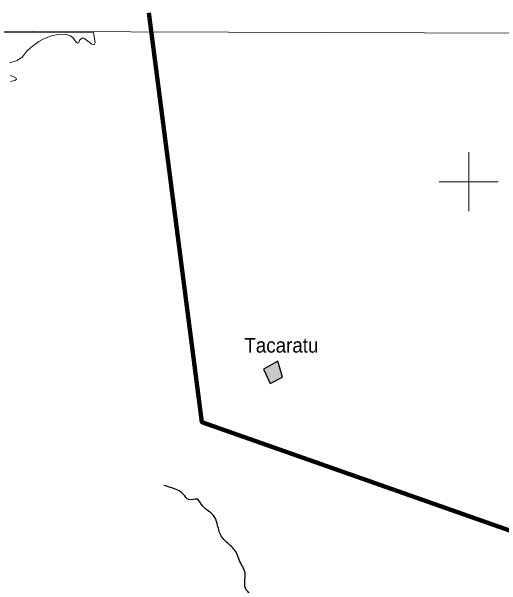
# Model space of a CAD drawing. Extents: x -1643653 to 4543381, y 1624270 to 13878484.
# Drawn here: x 584514 to 601111, y 8986338 to 9005760 of the extents above; entities that cross this region are included whole.
import ezdxf

# ---------------------------------------------------------------- set-up
doc = ezdxf.new("R2010")
doc.units = 0
doc.header["$LTSCALE"] = 200
for name, color, linetype, lineweight in [('1', 7, 'Continuous', 13), ('2', 7, 'Continuous', 13), ('21', 7, 'Continuous', 25), ('24', 7, 'Continuous', 25), ('25', 7, 'Continuous', 13), ('60', 7, 'Continuous', 13), ('9', 7, 'Continuous', 90)]:
    doc.layers.add(name, color=color, linetype=linetype, lineweight=lineweight)
doc.layers.add('41', color=7, linetype='Continuous')

msp = doc.modelspace()

# ---------------------------------------------------------------- hatches: boundary and pattern name
at = {"layer": '21'}
msp.add_hatch(color=256, dxfattribs=at).paths.add_polyline_path([(593047.1, 8993652.8), (593274.2, 8993173.1), (593688.7, 8993391.5), (593540, 8993932.9)])

# ---------------------------------------------------------------- linework, layer by layer
at = {"layer": '1'}
msp.add_lwpolyline([(565303.2, 9005146.6), (664889.8, 9004806.7), (719872.1, 9004543.9), (790635.8, 9004109)], dxfattribs=at)
at = {"layer": '2'}
for p, q in [((600000, 8999000), (600000, 9001000)), ((599000, 9000000), (601000, 9000000))]:
    msp.add_line(p, q, dxfattribs=at)
at = {"layer": '21'}
msp.add_lwpolyline([(593047.1, 8993652.8), (593274.2, 8993173.1), (593688.7, 8993391.5), (593540, 8993932.9)], close=True, dxfattribs=at)
at = {"layer": '24'}
msp.add_spline([(593232.1, 8979422.6), (593198.8, 8979610.9), (593054.8, 8979777.1), (592988.4, 8979954.4), (592877.6, 8980164.9), (592722.6, 8980286.8), (592611.8, 8980375.4), (592456.8, 8980729.9), (592146.7, 8981173.1), (591936.2, 8981505.4), (591869.8, 8981682.7), (591814.4, 8981815.7), (591504.3, 8981904.3), (591316, 8982048.3), (591216.4, 8982148), (591072.4, 8982347.5), (591183.1, 8982491.5), (591526.5, 8982834.9), (591637.2, 8983134.1), (591980.6, 8983211.6), (591958.4, 8983388.9), (591925.2, 8983544), (592146.7, 8983832), (592445.7, 8983865.3), (592589.7, 8983987.2), (592600.8, 8984208.7), (592778, 8984507.9), (592656.1, 8984718.4), (592478.9, 8984851.3), (592456.8, 8985084), (592589.7, 8985228), (592634, 8985394.2), (592645.1, 8985826.3), (592645.1, 8985970.3), (592467.9, 8986191.9), (592423.5, 8986763.6), (592224.2, 8987206.8), (592124.5, 8987461.6), (591847.6, 8987760.7), (591604, 8988037.7), (591482.1, 8988436.5), (591360.3, 8988702.4), (590950.5, 8989079.1), (590806.6, 8989256.4), (590518.6, 8989245.3), (590341.4, 8989422.6), (590031.3, 8989610.9), (589676.9, 8989721.7)], degree=3, dxfattribs=at)
at = {"layer": '25'}
msp.add_line((587296.7, 9005052), (574348.1, 9005079.3), dxfattribs=at)
for points in [[(584458.5, 9004027.7), (584711.2, 9004098.9), (584888.4, 9004222.2), (585025.2, 9004408.7), (585173.7, 9004544.1), (585437.6, 9004740.9), (585593, 9004823), (585860.5, 9004930.9), (586094, 9004976.5), (586360.6, 9004989.5), (586505.2, 9004940), (586587.3, 9004879.5), (586702.2, 9004719.4), (586749.8, 9004689.2), (586792.6, 9004706), (586819.4, 9004784.7), (586914.3, 9004864.1), (586966.1, 9004855.3), (587240.7, 9004654.4), (587315.8, 9004635.1), (587350.6, 9004699.9), (587296.7, 9005052)], [(584458.5, 9004027.7), (584711.2, 9004098.9), (584888.4, 9004222.2), (585025.2, 9004408.7), (585173.7, 9004544.1), (585437.6, 9004740.9), (585593, 9004823), (585860.5, 9004930.9), (586094, 9004976.5), (586360.6, 9004989.5), (586505.2, 9004940), (586587.3, 9004879.5), (586702.2, 9004719.4), (586749.8, 9004689.2), (586792.6, 9004706), (586819.4, 9004784.7), (586914.3, 9004864.1), (586966.1, 9004855.3), (587240.7, 9004654.4), (587315.8, 9004635.1), (587350.6, 9004699.9), (587296.7, 9005052)], [(584481.8, 9003391.9), (584629.6, 9003423.7), (584682.7, 9003471.9), (584658.6, 9003520.2), (584473.2, 9003604)], [(584481.8, 9003391.9), (584629.6, 9003423.7), (584682.7, 9003471.9), (584658.6, 9003520.2), (584473.2, 9003604)]]:
    msp.add_lwpolyline(points, dxfattribs=at)
at = {"layer": '60', "lineweight": 25}
msp.add_spline([(814781, 9009175.5), (814787.2, 9009173.4), (814796.9, 9009173.4), (814799.4, 9009172.4), (814805.1, 9009174.5), (814805.6, 9009176.5), (814811.7, 9009179.5), (814811.7, 9009179.5), (814801.5, 9009181), (814790.7, 9009181.5), (814784.1, 9009183.1), (814777.4, 9009185.1), (814778.4, 9009175.5)], degree=3, dxfattribs=at)
at = {"layer": '9'}
msp.add_lwpolyline([(605873.8, 8986618.4), (590956.6, 8991866.7), (589163, 9005713.7)], dxfattribs=at)

# ---------------------------------------------------------------- texts
at = {"layer": '41', "width": 0.95}
msp.add_text('Tacaratu', height=500, dxfattribs=at).set_placement((592402.2, 8994216.5))

doc.saveas('drawing.dxf')
